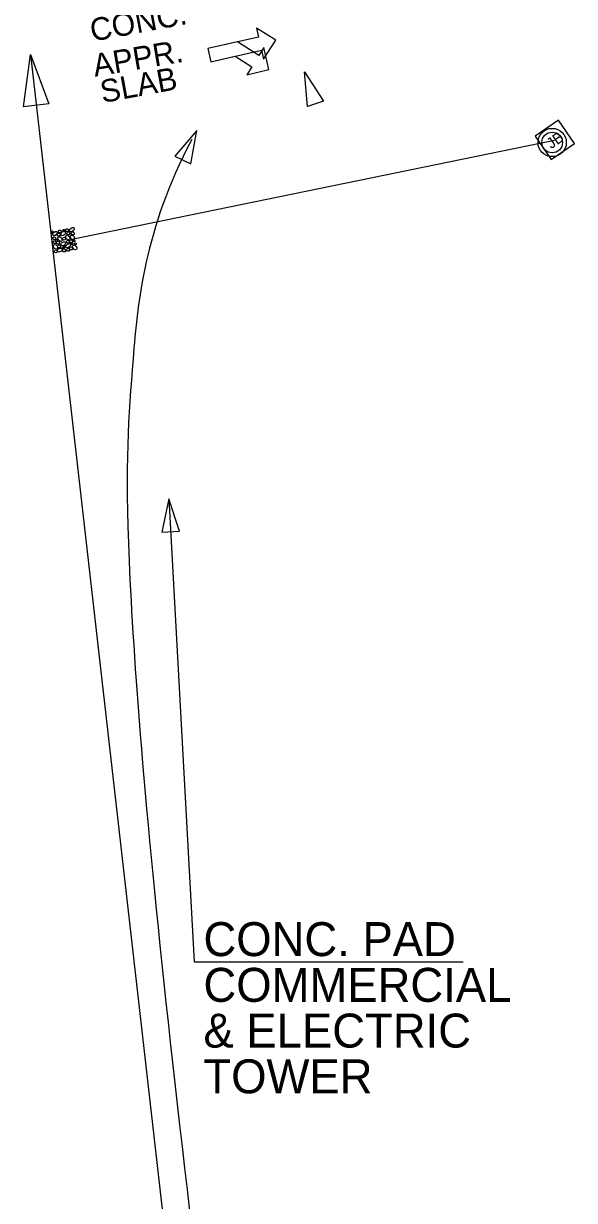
# Model space of a CAD drawing. Extents: x 16382402 to 16388022, y 46194326 to 46202918.
# Drawn here: x 16384949.9 to 16385047.2, y 46194798.9 to 46195006.8 of the extents above; entities that cross this region are included whole.
import ezdxf

# ---------------------------------------------------------------- set-up
doc = ezdxf.new("R2010")
doc.units = 0
for name, color, linetype in [('Default', 7, 'Continuous'), ('RD_EX_Bridge', 7, 'Continuous'), ('RD_EX_DR_Inlet', 7, 'Continuous'), ('RD_EX_GuardRail', 7, 'Continuous'), ('RD_PD_ALT2_TX', 7, 'Continuous'), ('RD_PD_Final_LnLine', 7, 'Continuous'), ('RD_PD_Final_TX', 7, 'Continuous'), ('RD_TX_Drainage', 7, 'Continuous')]:
    doc.layers.add(name, color=color, linetype=linetype)

msp = doc.modelspace()

# ---------------------------------------------------------------- linework, layer by layer
at = {"layer": 'RD_EX_Bridge'}
msp.add_line((16384951.1, 46195001.3), (16384980.81, 46194741.12), dxfattribs=at)
at = {"layer": 'RD_EX_DR_Inlet'}
msp.add_line((16385047.19, 46194985.63), (16385044.34, 46194989.74), dxfattribs=at)
msp.add_lwpolyline([(16385047.19, 46194985.63), (16385044.34, 46194989.74), (16385040.23, 46194986.89), (16385043.07, 46194982.78)], close=True, dxfattribs=at)
at = {"layer": 'RD_EX_GuardRail'}
for p, q in [((16384975.54, 46194922.83), (16384980.04, 46194841.04)), ((16384980.04, 46194841.04), (16385027.54, 46194841.04))]:
    msp.add_line(p, q, dxfattribs=at)
at = {"layer": 'RD_PD_ALT2_TX'}
msp.add_open_spline([(16384979.58, 46194986.31), (16384971.13, 46194970.09), (16384968.98, 46194945.44), (16384967.21, 46194921.07), (16384973.36, 46194841.3), (16384985.67, 46194744.46), (16384986.24, 46194723.05)], degree=3, dxfattribs=at)
at = {"layer": 'RD_PD_Final_LnLine'}
for points in [[(16384982.45, 46195002.38), (16384982.98, 46195000.04), (16384991.93, 46195002.07), (16384992.29, 46195000.48), (16384994.42, 46195003.86), (16384991.04, 46195006), (16384991.4, 46195004.41)], [(16384982.45, 46195002.38), (16384982.98, 46195000.04), (16384987.25, 46195001.01), (16384990.18, 46194999.14), (16384989.31, 46194997.76), (16384993.21, 46194998.65), (16384992.33, 46195002.55), (16384991.46, 46195001.17), (16384987.67, 46195003.56)]]:
    msp.add_lwpolyline(points, close=True, dxfattribs=at)
at = {"layer": 'RD_PD_Final_TX'}
for points in [[(16384954.82, 46194969.99), (16384954.89, 46194970.12), (16384955.02, 46194970.15), (16384955.13, 46194970.06), (16384955.14, 46194969.93), (16384955.06, 46194969.85), (16384954.93, 46194969.84), (16384954.86, 46194969.89), (16384954.82, 46194969.99)], [(16384955.21, 46194969.89), (16384955.45, 46194970.04), (16384955.69, 46194970.05), (16384955.82, 46194969.96), (16384955.85, 46194969.77), (16384955.71, 46194969.52), (16384955.47, 46194969.35), (16384955.22, 46194969.3), (16384955.06, 46194969.38), (16384955.02, 46194969.58), (16384955.1, 46194969.77), (16384955.22, 46194969.9)], [(16384955.85, 46194969.49), (16384955.95, 46194969.7), (16384956.17, 46194969.75), (16384956.35, 46194969.62), (16384956.36, 46194969.39), (16384956.25, 46194969.26), (16384956.03, 46194969.24), (16384955.91, 46194969.32), (16384955.85, 46194969.49)], [(16384956.02, 46194970.05), (16384956.13, 46194970.27), (16384956.35, 46194970.32), (16384956.53, 46194970.18), (16384956.54, 46194969.95), (16384956.42, 46194969.82), (16384956.2, 46194969.8), (16384956.08, 46194969.88), (16384956.02, 46194970.05)], [(16384956.65, 46194969.91), (16384956.89, 46194970.05), (16384957.13, 46194970.07), (16384957.26, 46194969.98), (16384957.29, 46194969.79), (16384957.15, 46194969.54), (16384956.91, 46194969.37), (16384956.66, 46194969.32), (16384956.5, 46194969.4), (16384956.46, 46194969.59), (16384956.54, 46194969.79), (16384956.66, 46194969.92)], [(16384956.85, 46194970.26), (16384956.91, 46194970.4), (16384957.04, 46194970.42), (16384957.15, 46194970.34), (16384957.16, 46194970.21), (16384957.09, 46194970.13), (16384956.96, 46194970.11), (16384956.89, 46194970.16), (16384956.85, 46194970.26)], [(16384957.31, 46194970.29), (16384957.42, 46194970.5), (16384957.64, 46194970.55), (16384957.81, 46194970.42), (16384957.83, 46194970.19), (16384957.71, 46194970.06), (16384957.49, 46194970.04), (16384957.37, 46194970.12), (16384957.31, 46194970.29)], [(16384957.53, 46194969.72), (16384957.64, 46194969.94), (16384957.86, 46194969.98), (16384958.04, 46194969.85), (16384958.05, 46194969.62), (16384957.93, 46194969.49), (16384957.71, 46194969.47), (16384957.6, 46194969.55), (16384957.53, 46194969.72)], [(16384958.21, 46194970.59), (16384958.46, 46194970.74), (16384958.7, 46194970.75), (16384958.83, 46194970.66), (16384958.85, 46194970.47), (16384958.72, 46194970.22), (16384958.47, 46194970.05), (16384958.22, 46194970), (16384958.07, 46194970.08), (16384958.02, 46194970.28), (16384958.11, 46194970.47), (16384958.22, 46194970.6)], [(16384958.31, 46194969.72), (16384958.42, 46194969.94), (16384958.64, 46194969.99), (16384958.81, 46194969.85), (16384958.83, 46194969.62), (16384958.71, 46194969.49), (16384958.49, 46194969.47), (16384958.37, 46194969.55), (16384958.31, 46194969.72)], [(16384955.04, 46194968.85), (16384955.15, 46194969.07), (16384955.36, 46194969.12), (16384955.54, 46194968.98), (16384955.56, 46194968.76), (16384955.44, 46194968.62), (16384955.22, 46194968.6), (16384955.1, 46194968.68), (16384955.04, 46194968.85)], [(16384955.11, 46194968.16), (16384955.22, 46194968.38), (16384955.43, 46194968.43), (16384955.61, 46194968.29), (16384955.63, 46194968.07), (16384955.51, 46194967.93), (16384955.29, 46194967.91), (16384955.17, 46194968), (16384955.11, 46194968.16)], [(16384955.74, 46194967.59), (16384955.89, 46194967.34), (16384955.91, 46194967.1), (16384955.82, 46194966.97), (16384955.62, 46194966.94), (16384955.38, 46194967.08), (16384955.2, 46194967.32), (16384955.16, 46194967.57), (16384955.23, 46194967.73), (16384955.43, 46194967.78), (16384955.63, 46194967.69), (16384955.75, 46194967.58)], [(16384955.58, 46194968.52), (16384955.64, 46194968.65), (16384955.77, 46194968.68), (16384955.88, 46194968.6), (16384955.89, 46194968.47), (16384955.82, 46194968.39), (16384955.69, 46194968.37), (16384955.61, 46194968.42), (16384955.58, 46194968.52)], [(16384955.72, 46194968.06), (16384955.83, 46194968.28), (16384956.05, 46194968.33), (16384956.23, 46194968.19), (16384956.24, 46194967.97), (16384956.12, 46194967.83), (16384955.9, 46194967.81), (16384955.79, 46194967.89), (16384955.73, 46194968.06)], [(16384955.89, 46194967.42), (16384956, 46194967.64), (16384956.22, 46194967.69), (16384956.39, 46194967.55), (16384956.41, 46194967.33), (16384956.29, 46194967.19), (16384956.07, 46194967.17), (16384955.95, 46194967.26), (16384955.89, 46194967.42)], [(16384956.51, 46194968.94), (16384956.66, 46194968.7), (16384956.67, 46194968.46), (16384956.58, 46194968.33), (16384956.39, 46194968.3), (16384956.14, 46194968.44), (16384955.97, 46194968.68), (16384955.93, 46194968.93), (16384956, 46194969.09), (16384956.2, 46194969.13), (16384956.4, 46194969.05), (16384956.52, 46194968.93)], [(16384956.68, 46194968.09), (16384956.92, 46194968.24), (16384957.16, 46194968.26), (16384957.29, 46194968.17), (16384957.32, 46194967.97), (16384957.18, 46194967.73), (16384956.94, 46194967.55), (16384956.69, 46194967.51), (16384956.54, 46194967.58), (16384956.49, 46194967.78), (16384956.58, 46194967.98), (16384956.69, 46194968.1)], [(16384956.79, 46194968.79), (16384956.9, 46194969.01), (16384957.12, 46194969.06), (16384957.3, 46194968.92), (16384957.31, 46194968.69), (16384957.19, 46194968.56), (16384956.97, 46194968.54), (16384956.85, 46194968.62), (16384956.79, 46194968.79)], [(16384956.98, 46194967.43), (16384957.04, 46194967.56), (16384957.17, 46194967.59), (16384957.28, 46194967.51), (16384957.29, 46194967.37), (16384957.22, 46194967.29), (16384957.08, 46194967.28), (16384957.01, 46194967.33), (16384956.98, 46194967.43)], [(16384957.91, 46194969.2), (16384958.06, 46194968.96), (16384958.07, 46194968.72), (16384957.98, 46194968.59), (16384957.79, 46194968.56), (16384957.54, 46194968.7), (16384957.37, 46194968.94), (16384957.33, 46194969.19), (16384957.4, 46194969.35), (16384957.6, 46194969.39), (16384957.8, 46194969.31), (16384957.92, 46194969.19)], [(16384957.56, 46194967.76), (16384957.8, 46194967.9), (16384958.04, 46194967.92), (16384958.17, 46194967.83), (16384958.2, 46194967.64), (16384958.06, 46194967.39), (16384957.82, 46194967.22), (16384957.57, 46194967.17), (16384957.41, 46194967.25), (16384957.37, 46194967.45), (16384957.45, 46194967.64), (16384957.57, 46194967.77)], [(16384957.45, 46194968.24), (16384957.56, 46194968.45), (16384957.77, 46194968.5), (16384957.95, 46194968.37), (16384957.97, 46194968.14), (16384957.85, 46194968.01), (16384957.63, 46194967.99), (16384957.51, 46194968.07), (16384957.45, 46194968.24)], [(16384958.02, 46194968.32), (16384958.13, 46194968.54), (16384958.34, 46194968.59), (16384958.52, 46194968.45), (16384958.54, 46194968.22), (16384958.42, 46194968.09), (16384958.2, 46194968.07), (16384958.08, 46194968.15), (16384958.02, 46194968.32)], [(16384958.75, 46194969.21), (16384958.9, 46194968.97), (16384958.91, 46194968.73), (16384958.82, 46194968.6), (16384958.63, 46194968.57), (16384958.38, 46194968.7), (16384958.21, 46194968.95), (16384958.17, 46194969.2), (16384958.24, 46194969.35), (16384958.44, 46194969.4), (16384958.64, 46194969.31), (16384958.76, 46194969.2)], [(16384958.3, 46194967.88), (16384958.36, 46194968.01), (16384958.49, 46194968.04), (16384958.6, 46194967.95), (16384958.61, 46194967.82), (16384958.54, 46194967.74), (16384958.4, 46194967.73), (16384958.33, 46194967.78), (16384958.3, 46194967.88)], [(16384959.14, 46194967.46), (16384959.28, 46194967.22), (16384959.3, 46194966.98), (16384959.21, 46194966.85), (16384959.02, 46194966.82), (16384958.77, 46194966.96), (16384958.59, 46194967.2), (16384958.55, 46194967.45), (16384958.63, 46194967.61), (16384958.82, 46194967.65), (16384959.02, 46194967.56), (16384959.14, 46194967.45)], [(16384958.66, 46194968.36), (16384958.72, 46194968.49), (16384958.85, 46194968.52), (16384958.96, 46194968.44), (16384958.97, 46194968.3), (16384958.9, 46194968.22), (16384958.77, 46194968.21), (16384958.69, 46194968.26), (16384958.66, 46194968.36)], [(16384958.86, 46194967.87), (16384958.92, 46194968), (16384959.05, 46194968.03), (16384959.16, 46194967.94), (16384959.17, 46194967.81), (16384959.1, 46194967.73), (16384958.96, 46194967.72), (16384958.89, 46194967.77), (16384958.86, 46194967.87)], [(16384955.31, 46194966.55), (16384955.42, 46194966.77), (16384955.64, 46194966.82), (16384955.82, 46194966.68), (16384955.83, 46194966.45), (16384955.71, 46194966.32), (16384955.49, 46194966.3), (16384955.37, 46194966.38), (16384955.31, 46194966.55)], [(16384956.06, 46194966.98), (16384956.3, 46194967.12), (16384956.54, 46194967.14), (16384956.67, 46194967.05), (16384956.7, 46194966.86), (16384956.56, 46194966.61), (16384956.32, 46194966.44), (16384956.07, 46194966.39), (16384955.92, 46194966.47), (16384955.87, 46194966.67), (16384955.96, 46194966.86), (16384956.07, 46194966.99)], [(16384956.73, 46194967.15), (16384956.79, 46194967.28), (16384956.93, 46194967.31), (16384957.03, 46194967.22), (16384957.04, 46194967.09), (16384956.97, 46194967.01), (16384956.84, 46194967), (16384956.77, 46194967.05), (16384956.73, 46194967.15)], [(16384956.79, 46194966.71), (16384956.9, 46194966.93), (16384957.12, 46194966.98), (16384957.3, 46194966.84), (16384957.31, 46194966.62), (16384957.19, 46194966.48), (16384956.97, 46194966.46), (16384956.85, 46194966.55), (16384956.79, 46194966.71)], [(16384957.5, 46194966.83), (16384957.61, 46194967.05), (16384957.83, 46194967.1), (16384958.01, 46194966.97), (16384958.02, 46194966.74), (16384957.9, 46194966.6), (16384957.68, 46194966.59), (16384957.56, 46194966.67), (16384957.5, 46194966.83)], [(16384958.02, 46194967.06), (16384958.12, 46194967.28), (16384958.34, 46194967.33), (16384958.52, 46194967.2), (16384958.53, 46194966.97), (16384958.42, 46194966.83), (16384958.2, 46194966.82), (16384958.08, 46194966.9), (16384958.02, 46194967.06)]]:
    msp.add_lwpolyline(points, dxfattribs=at)
at = {"layer": 'RD_TX_Drainage'}
for p, q in [((16385043.25, 46194987.62), (16385043.25, 46194987.62)), ((16385043.25, 46194987.62), (16385043.25, 46194987.62)), ((16385043.65, 46194986.12), (16384958.42, 46194968.65)), ((16385041.42, 46194985.78), (16385041.42, 46194985.78)), ((16385043.25, 46194985.78), (16385043.25, 46194985.78)), ((16385043.25, 46194985.78), (16385043.25, 46194985.78)), ((16385045.08, 46194985.78), (16385045.08, 46194985.78)), ((16385043.25, 46194983.95), (16385043.25, 46194983.95)), ((16385043.25, 46194983.95), (16385043.25, 46194983.95))]:
    msp.add_line(p, q, dxfattribs=at)
for points in [[(16384949.88, 46194992.1), (16384951.1, 46195001.3), (16384954.35, 46194992.61)], [(16385000.02, 46194992.12), (16384999.5, 46194998.28), (16385002.86, 46194993.08)], [(16384979.43, 46194982.02), (16384980.48, 46194987.92), (16384976.62, 46194983.34)], [(16384977.41, 46194917.13), (16384975.54, 46194922.83), (16384974.31, 46194916.95)]]:
    msp.add_lwpolyline(points, close=True, dxfattribs=at)
for radius in [2.5, 1.83]:
    msp.add_circle((16385043.25, 46194985.78), radius, dxfattribs=at)

# ---------------------------------------------------------------- texts
at = {"layer": 'Default'}
for s, rotation, p in [('CONC.', 10.5155, (16384962.03, 46195003.59)), ('APPR.', 9.5796, (16384962.48, 46194997.39)), ('SLAB', 10.4924, (16384963.83, 46194992.74))]:
    msp.add_text(s, height=4, rotation=rotation, dxfattribs=at).set_placement(p)
at = {"layer": 'RD_EX_DR_Inlet'}
msp.add_text('JB', height=1.875, rotation=34.6953, dxfattribs=at).set_placement((16385043.08, 46194984.59))
at = {"layer": 'RD_EX_GuardRail'}
for s, p in [('CONC. PAD', (16384981.66, 46194842.04)), ('COMMERCIAL ', (16384981.66, 46194833.96)), ('& ELECTRIC', (16384981.66, 46194825.88)), ('TOWER', (16384981.66, 46194817.8))]:
    msp.add_text(s, height=6, dxfattribs=at).set_placement(p)

doc.saveas('drawing.dxf')
